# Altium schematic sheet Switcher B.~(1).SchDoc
size 431 x 279 mm; Organization: UTVATE; Address1: ADDRESS 1; Address2: ADDRESS 2; Address3: ADDRESS 3; Address4: ADDRESS 4; Revision: -; SheetNumber: 1; SheetTotal: 1; ENG_APP_DATE: YYYY/MM/DD; DSN_APP_DATE: YYYY/MM/DD; CHK_APP_DATE: YYYY/MM/DD
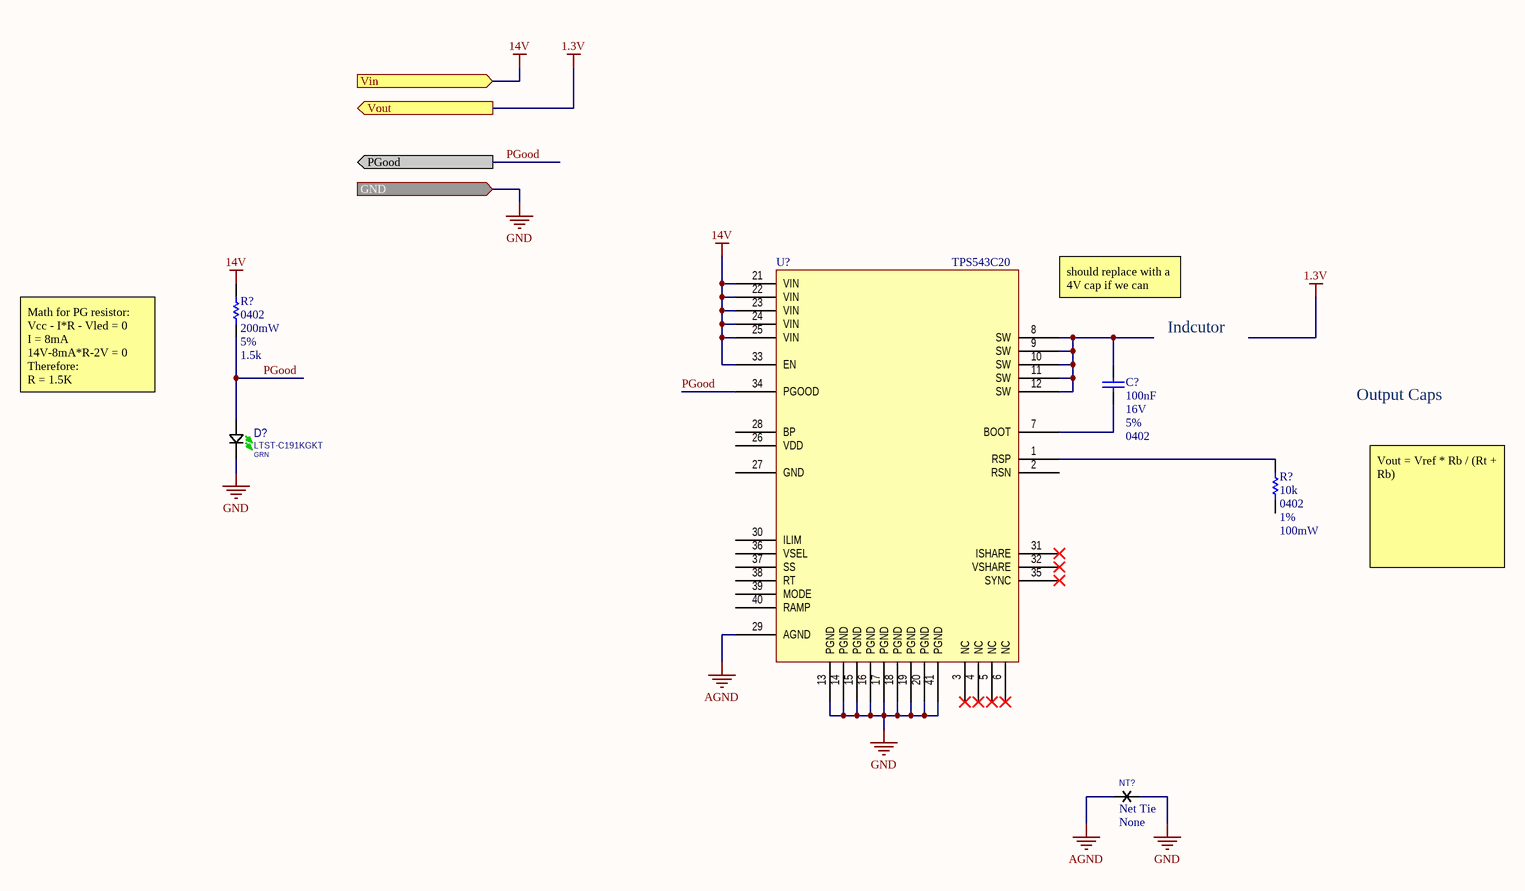
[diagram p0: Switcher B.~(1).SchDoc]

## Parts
(Parts that share a designator on the sheet are numbered #1, #2 ... from top to bottom, then left to right.)
C?  value 100nF  Voltage Rating: 16V  Tolerance: 5%  Case/Package: 0402  [CAP_0402_Nominal]  (hidden comment: GRM155R71C104JA88D)
D?  LTST-C191KGKT  Color: GRN  [DIOC1608X06N]
NT?  Net Tie  Manufacturer: None  [Net Tie-Footprint-1]  (net tie, no BOM)
R?#1  value 1.5k  Case/Package: 0402  Power: 200mW  Tolerance: 5%  [RESC1005X40X25ML05T10]  (hidden comment: RCS04021K50JNED)
R?#2  value 10k  Case/Package: 0402  Tolerance: 1%  Power: 100mW  [RES_0402_Most]  (hidden comment: ERJ-2RKF1002X)
U?  TPS543C20  [TPS543C20 -Footprint-1]

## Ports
GND (in), PGood (out), Vin (in), Vout (out)

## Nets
14V: R?#1.2 U?.21(VIN) U?.22(VIN) U?.23(VIN) U?.24(VIN) U?.25(VIN) U?.33(EN) ; port Vin
AGND: NT?.1 U?.29(AGND)
GND: D?.1 NT?.2 U?.13(PGND) U?.14(PGND) U?.15(PGND) U?.16(PGND) U?.17(PGND) U?.18(PGND) U?.19(PGND) U?.20(PGND) U?.41(PGND) ; port GND
PGood: D?.2 R?#1.1 U?.34(PGOOD) ; port PGood
NetC?_1: C?.1 U?.7(BOOT)
NetC?_2: C?.2 U?.8(SW) U?.9(SW) U?.10(SW) U?.11(SW) U?.12(SW)
NetR?#2_1: R?#2.1 U?.1(RSP)

Not connected (* = marked no-connect by the designer): R?#2 2; U? 2(RSN) 3(NC)* 4(NC)* 5(NC)* 6(NC)* 26(VDD) 27(GND) 28(BP) 30(ILIM) 31(ISHARE)* 32(VSHARE)* 35(SYNC)* 36(VSEL) 37(SS) 38(RT) 39(MODE) 40(RAMP)

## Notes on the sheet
- (near U?) should replace with a 4V cap if we can
- Indcutor
- Math for PG resistor:
  Vcc - I*R - Vled = 0
  I = 8mA
  14V-8mA*R-2V = 0
  Therefore:
  R = 1.5K
- Output Caps
- Vout = Vref * Rb / (Rt + Rb)

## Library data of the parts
C? = CMP-001-00001-23: Cap 100nF 0402 16V; Manufacturer: Murata; Capacitor Type: Ceramic; Dielectric: X7R
D? = CMP-011-0002-3: LED, GREEN, 0603, 2V; Manufacturer: Lite-On Inc.; Forward Current: 20mA
NT? = CMP-006-0011-2: All Copper net tie to join two nets together in a specific location
R?#1 = CMP-009-00072-1: Res 1.5K 0402; Manufacturer: Vishay Dale
R?#2 = CMP-009-00012-12: Res 10k 0402; Manufacturer: Panasonic; Temperature Coefficient: 100ppm/°C; Voltage Rating: 50V
U? = CMP-019-00006-1: Switching Regulator, Current-mode, 40A, 2000kHz Switching Freq-Max, PQCC40; Manufacturer: Texas Instruments; Min Supply Voltage: 4V; Output Voltage: 5.5V; Max Supply Voltage: 16V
